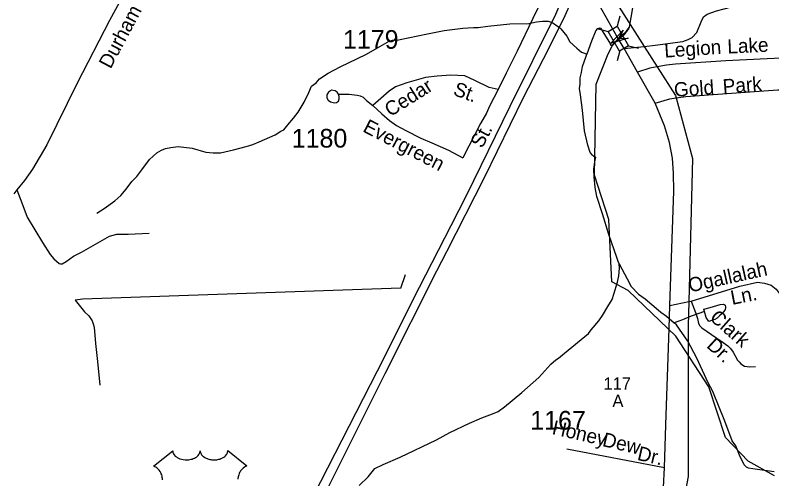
# Model space of a CAD drawing. Extents: x 2260773 to 2342389, y 552869 to 618546.
# Drawn here: x 2283170 to 2288230, y 568758 to 571861 of the extents above; entities that cross this region are included whole.
import ezdxf

# ---------------------------------------------------------------- set-up
doc = ezdxf.new("R2010")
doc.units = 0
for name, color, linetype in [('Exist Boundary Political Urban Extension UEB', 7, 'Continuous'), ('Exist Hydrographic Creek Single Shore', 7, 'Continuous'), ('Exist Hydrographic Misc Water Feature', 7, 'Continuous'), ('Exist Road Non-System Type 51', 7, 'Continuous'), ('Exist Road Non-System Type 51 Label', 7, 'Continuous'), ('Exist Road Primary US Attributed', 7, 'Continuous'), ('Exist Road Primary US Divided Attributed', 7, 'Continuous'), ('Exist Road Primary US Label', 7, 'Continuous'), ('Exist Road Primary US Shield CELL', 7, 'Continuous'), ('Exist Road Primary US Structure Standard Bridge CELL', 7, 'Continuous'), ('Exist Road Secondary Structure Standard Bridge Attributed CELL', 7, 'Continuous'), ('Exist Road Secondary Type 51 Attributed', 7, 'Continuous'), ('Exist Road Secondary Type 51 Label', 7, 'Continuous'), ('Exist Road Secondary Type 51 Number Label', 7, 'Continuous')]:
    doc.layers.add(name, color=color, linetype=linetype)

msp = doc.modelspace()

# ---------------------------------------------------------------- linework, layer by layer
at = {"layer": 'Exist Boundary Political Urban Extension UEB'}
msp.add_line((2287376.6, 571652.3), (2287464, 571515.1), dxfattribs=at)
for points in [[(2288406.6, 572860.4), (2287194.1, 571939.1), (2287376.6, 571652.3)], [(2287464, 571515.1), (2287586.5, 571322.6), (2287590.4, 571307.9)], [(2287590.4, 571307.9), (2287698.5, 570902.3), (2287674.6, 569943.9)], [(2287674.6, 569943.9), (2287670.5, 569781.5), (2287670.5, 568772.8), (2287558.4, 568184.4), (2287278.2, 567147.7), (2287255.6, 567057.4)]]:
    msp.add_lwpolyline(points, dxfattribs=at)
at = {"layer": 'Exist Hydrographic Creek Single Shore'}
for points in [[(2287160, 570075.5), (2287139.9, 570492.5), (2287044.9, 570789.5), (2287055.8, 571399.3), (2287135.6, 571602), (2287164.2, 571658.1), (2287204.2, 571703.8), (2287256.8, 571750.7), (2287278.5, 571781.6), (2287300.8, 571909.2)], [(2288246.9, 568777.9), (2288070.8, 568876.5), (2287919.9, 569033.7), (2287807.9, 569373.8), (2287587.9, 569712.7), (2287268.8, 570017.6), (2287160, 570075.5)]]:
    msp.add_lwpolyline(points, dxfattribs=at)
at = {"layer": 'Exist Hydrographic Misc Water Feature'}
for points in [[(2283715.5, 570536.2), (2283765.1, 570566.9), (2283836.3, 570619.4), (2283876.1, 570654), (2283911.5, 570696), (2283949.3, 570748.4), (2283983.1, 570781), (2284016.7, 570827), (2284067.6, 570895.6), (2284117.6, 570939.9), (2284149.4, 570958.2), (2284175, 570968.6), (2284210.9, 570975), (2284260.9, 570981.2), (2284353, 570970.2), (2284445.3, 570944.9), (2284494.9, 570939.5), (2284543.1, 570939.9), (2284630.6, 570958.8), (2284714.3, 570981.4), (2284758.4, 570995.9), (2284802.5, 571012.4), (2284908.1, 571059.3), (2284945.6, 571083.7), (2284967.7, 571093.7), (2284993, 571126), (2285031.1, 571170.6), (2285062.5, 571210.8), (2285103.5, 571278.8), (2285133, 571343.4), (2285152.7, 571385.4), (2285182.2, 571407.7), (2285205.8, 571433.8), (2285263.6, 571472.5), (2285343.4, 571515.2), (2285458.4, 571570.1), (2285520.6, 571600.9), (2285594, 571643.4), (2285671.5, 571688), (2285693.4, 571694.5), (2285733.2, 571696.6), (2285926.8, 571736.4), (2286038.3, 571757.7), (2286164.4, 571774.8), (2286234.6, 571779.2), (2286266.5, 571777.6), (2286330.1, 571786.4), (2286478, 571803.8), (2286605.9, 571804.8), (2286655.7, 571817.2), (2286695.5, 571819.7), (2286711.3, 571819.7), (2286733.5, 571820), (2286765.4, 571810.3), (2286773.8, 571802.2), (2286810.3, 571778.9), (2286820.2, 571768.9), (2286858.7, 571719.3), (2286878.6, 571681.4), (2286925.4, 571639.9), (2286957.2, 571614.4), (2286977.7, 571606.5), (2286993.7, 571600.8)], [(2287156.7, 571656.1), (2287146.8, 571677.9), (2287098, 571755.4), (2287096, 571761.4), (2287088, 571771.5), (2287078.1, 571773.4), (2287062.1, 571769.3), (2287053.9, 571759.2), (2287025, 571686.9), (2286993.7, 571600.8)], [(2287156.7, 571656.1), (2287196.9, 571690.6), (2287247.9, 571736.9), (2287260, 571750.9), (2287275.6, 571773.2)], [(2287054.2, 570909.6), (2287049.8, 570909.4), (2287038, 570917.3), (2287029.8, 570923.4), (2287015.6, 570941.4), (2286999.2, 570991.3), (2286978.3, 571086.9), (2286965, 571224.7), (2286950, 571328.4), (2286943.8, 571370.2), (2286949.2, 571400.3), (2286949, 571442.5), (2286956.8, 571476.2), (2286964.3, 571516.4), (2286987.5, 571586.7), (2286993.7, 571600.8)], [(2287204.7, 570205.2), (2287194.6, 570239.2), (2287141.1, 570392.9), (2287097.6, 570530.4), (2287060.7, 570647.8), (2287049.8, 570707.5), (2287043.1, 570779.5), (2287040.8, 570829.3), (2287046.2, 570879.6), (2287054.2, 570909.6)], [(2285471.4, 568714.1), (2285530.8, 568772.4), (2285576.3, 568826.8), (2285630.1, 568853.2), (2285743.7, 568902.2), (2285986.7, 569018.5), (2286075.8, 569067.5), (2286209.3, 569130.5), (2286290.9, 569167.3), (2286362.3, 569192.2), (2286400.2, 569208.4), (2286442.3, 569240.6), (2286559.2, 569335.7), (2286672.1, 569436.7), (2286753.1, 569525.5), (2286785.1, 569553.9), (2286802.8, 569565.8), (2286844.4, 569598.5), (2287005.1, 569731.7), (2287022.8, 569756.2), (2287072.4, 569814.4), (2287098, 569850.7), (2287133.1, 569911.1), (2287162.8, 569959.3), (2287174.5, 569993.3), (2287197.9, 570073.2), (2287207.5, 570117.6), (2287210.6, 570167.5), (2287209.2, 570196.8), (2287204.7, 570205.2)], [(2287204.7, 570205.2), (2287209.2, 570196.8), (2287263.3, 570095.8), (2287290.2, 570044.4), (2287338.4, 569994.9), (2287382.9, 569963.1), (2287471.6, 569886), (2287487.4, 569874.3), (2287525.8, 569846.7), (2287576.4, 569803)], [(2287779.4, 569879), (2287774.9, 569893.1), (2287817.4, 569905.4), (2287884.6, 569924), (2287904.9, 569926.2), (2287911.1, 569924.1), (2287918.9, 569920.5), (2287920.9, 569912.4), (2287920.9, 569902.3), (2287917.2, 569892.3), (2287909.2, 569878.1), (2287897.1, 569864.1), (2287879.7, 569848.1), (2287863.7, 569833.9), (2287847.9, 569823.7), (2287837.9, 569821.5), (2287808.1, 569811.4), (2287789.9, 569836.9), (2287779.4, 569879)], [(2287779.4, 569879), (2287689.8, 569846.3), (2287633.8, 569821.5), (2287608.2, 569813.5), (2287576.4, 569803)], [(2288245.3, 568804), (2288103.2, 568824.5), (2288074.9, 568830.4), (2288061, 568836.2), (2288045, 568852), (2288014.4, 568915.8), (2287989.6, 568979.5), (2287965.6, 569013.2), (2287916, 569144.7), (2287834.6, 569341.9), (2287803.6, 569401.3), (2287728.4, 569564.7), (2287667.3, 569679.8), (2287592.4, 569789.2), (2287576.4, 569803)]]:
    msp.add_lwpolyline(points, dxfattribs=at)
at = {"layer": 'Exist Road Non-System Type 51'}
for p, q in [((2287242, 571636.8), (2287376.6, 571652.3)), ((2285749, 570033.8), (2285780.3, 570126.1)), ((2287547.7, 569918.3), (2287674.6, 569943.9)), ((2287674.6, 569943.9), (2287691.1, 569947.2))]:
    msp.add_line(p, q, dxfattribs=at)
for points in [[(2287376.6, 571652.3), (2287450.9, 571660.9), (2287634.5, 571684.6), (2287670.3, 571697.1), (2287698.2, 571711.3), (2287727.9, 571745.5), (2287757.3, 571815.7), (2287773, 571849.9), (2287796.7, 571868), (2287860.5, 571890.7), (2287962.2, 571917.7), (2288029.8, 571964.3), (2288091.2, 572016.8), (2288114.9, 572040.9), (2288142.7, 572053.2), (2288164.7, 572053.3), (2288206.9, 572041.9), (2288259.1, 572016.2), (2288317.2, 571990.9), (2288381.4, 571981.6), (2288443.1, 571990.1), (2288479.2, 572002.4), (2288508.8, 572026.6), (2288511, 572030.6)], [(2288471.9, 571580.3), (2288337.2, 571575.2), (2287921.5, 571555.4), (2287586, 571532.2), (2287526.1, 571525.7), (2287464, 571515.1)], [(2287464, 571515.1), (2287414.4, 571506.7), (2287331.1, 571479.2)], [(2285333, 571331.3), (2285322.9, 571345.1), (2285308.9, 571355), (2285284.8, 571358.7), (2285265.1, 571344.7), (2285253.2, 571328.5), (2285253.4, 571308.5), (2285263.5, 571292.5), (2285279.6, 571280.8), (2285295.8, 571276.9), (2285307.7, 571275), (2285319.6, 571277.2), (2285331.5, 571285.1), (2285337.4, 571301.2), (2285337.4, 571317.2), (2285333, 571331.3)], [(2287590.4, 571307.9), (2287656, 571317.1), (2287961.5, 571337.9), (2288269.3, 571360.9), (2288399, 571362.1), (2288453.7, 571370.3)], [(2285333, 571331.3), (2285403.2, 571332.5), (2285456.8, 571326.7), (2285478, 571321.7), (2285498, 571311.9), (2285520, 571290.3), (2285562.1, 571255.9)], [(2287449.6, 571271.5), (2287548.2, 571302.1), (2287590.4, 571307.9)], [(2283182.2, 570691), (2283215.4, 570604.2), (2283249.2, 570510.3), (2283352.6, 570340.5), (2283404.9, 570260.1), (2283427.8, 570230.7), (2283463.6, 570200.1), (2283472.5, 570196.3), (2283485.3, 570197.5), (2283512.1, 570212.9), (2283560.5, 570247.3), (2283614, 570275.7), (2283800.4, 570381.4), (2283850.2, 570395.4), (2283925.5, 570395.4), (2284067.1, 570403.1)], [(2287691.1, 569947.2), (2288015.9, 570047.3), (2288134.3, 570074.9), (2288181.5, 570066.8), (2288225.4, 570053.1), (2288259.7, 570027.4), (2288298.7, 569973.6)], [(2285749, 570033.8), (2283621, 569959.9), (2283571.1, 569953.5), (2283633.7, 569876), (2283661.9, 569848.3), (2283684.2, 569814.6), (2283692.4, 569794.7), (2283698.8, 569772.7), (2283707.8, 569664.8), (2283720.9, 569543), (2283736.3, 569385.3)], [(2287691.1, 569947.2), (2287718.7, 569872.2), (2287733.1, 569831.4), (2287739.7, 569798.5), (2287747.6, 569782.7), (2287762.1, 569769.6), (2287862, 569699.8), (2287905.5, 569669.5), (2287937, 569648.5), (2287954.1, 569631.4), (2287971.2, 569606.4), (2288001.5, 569552.4), (2288012, 569540.6), (2288022.5, 569528.7), (2288047.5, 569512.9), (2288083, 569507.7), (2288119.9, 569510.3)]]:
    msp.add_lwpolyline(points, dxfattribs=at)
at = {"layer": 'Exist Road Primary US Attributed'}
for points in [[(2287196.9, 571715.9), (2287076.2, 571930.2), (2287035.8, 572001.3)], [(2287512.2, 568832.5), (2287521.5, 569120.3), (2287542.6, 569763.6), (2287547.7, 569918.3), (2287574.9, 570683.2), (2287572.2, 570804.5), (2287565.2, 570903.5), (2287545.7, 571009.4), (2287512.3, 571121), (2287449.6, 571271.5), (2287331.1, 571479.2), (2287242, 571636.8), (2287196.9, 571715.9)], [(2287018.9, 566693.9), (2287122, 567057.4), (2287159.7, 567190.1), (2287281, 567619.5), (2287342.7, 567854), (2287396.4, 568031.7), (2287443.8, 568215.9), (2287480.6, 568403.5), (2287496.4, 568528.5), (2287500.3, 568606.2), (2287505.6, 568701.6), (2287512.2, 568832.5)]]:
    msp.add_lwpolyline(points, dxfattribs=at)
at = {"layer": 'Exist Road Primary US Divided Attributed'}
for points in [[(2286878.6, 572105.8), (2286833, 571982.2), (2286782.4, 571865.7), (2286477.4, 571248.9), (2286185.2, 570652), (2286082.6, 570450.1), (2285871.7, 570038.9), (2285590.6, 569478.9), (2285164.4, 568647.3), (2284873.8, 568065.7), (2284671.9, 567618.8), (2284548.2, 567284.9), (2284478.2, 567045.3), (2284416.3, 566789.5), (2284365.2, 566533.7), (2284322.1, 566259.1), (2284289.8, 565936), (2284268.3, 565564.5), (2284273.7, 565214.4)], [(2284365.2, 565206.4), (2284354.4, 565561.8), (2284370.6, 565952.2), (2284397.5, 566242.9), (2284443.2, 566531), (2284491.7, 566784.1), (2284556.2, 567048), (2284618.1, 567263.4), (2284736.5, 567594.5), (2284938.3, 568065.7), (2285215.5, 568606.9), (2285643.3, 569463.1), (2285990.5, 570149.7), (2286057.7, 570278.9), (2286308, 570774.3), (2286569, 571310.1), (2286703.5, 571568.6), (2286838.1, 571837.8), (2286893.8, 571965.3), (2286930.4, 572091.7)]]:
    msp.add_lwpolyline(points, dxfattribs=at)
at = {"layer": 'Exist Road Primary US Shield CELL'}
msp.add_lwpolyline([(2284155, 568751.7), (2284154.7, 568759.3), (2284153.7, 568768.2), (2284152.1, 568776.7), (2284150.1, 568784.2), (2284146.9, 568792.7), (2284143.9, 568798.9), (2284139, 568807.4), (2284133.5, 568815.2), (2284127.9, 568821.6), (2284122.2, 568827.3), (2284116.7, 568831.5), (2284111.5, 568835.3), (2284105, 568839.2), (2284098.7, 568842.3), (2284094.7, 568843.9), (2284223.3, 568946.4), (2284223.6, 568941), (2284224.9, 568934.7), (2284225.9, 568931.5), (2284228.9, 568925.2), (2284233.7, 568917.9), (2284240.5, 568910.6), (2284248.2, 568904.3), (2284253.4, 568901), (2284262.1, 568896.3), (2284272.1, 568892.1), (2284283.2, 568888.9), (2284294.5, 568886.6), (2284306.9, 568885.3), (2284319.1, 568885), (2284332.3, 568886), (2284346.9, 568888.8), (2284353.7, 568890.6), (2284361.2, 568893.2), (2284368.2, 568896), (2284375.8, 568900.1), (2284382, 568904.1), (2284386.8, 568907.6), (2284393.7, 568914.1), (2284399.1, 568920.9), (2284401.4, 568924.7), (2284403.3, 568928.3), (2284406, 568936.1), (2284406.8, 568939.5), (2284407.3, 568946.6), (2284407.8, 568940.6), (2284408.4, 568936.9), (2284409.4, 568933.3), (2284410.9, 568929.4), (2284413.6, 568923.9), (2284416.7, 568919.4), (2284422.4, 568912.6), (2284426, 568909.3), (2284429.2, 568906.6), (2284438, 568900.6), (2284448.2, 568895.4), (2284453.2, 568893.2), (2284458.4, 568891.4), (2284464.9, 568889.4), (2284471.6, 568887.8), (2284478.3, 568886.7), (2284485.2, 568885.7), (2284492.2, 568885.2), (2284497.9, 568885), (2284504.8, 568885.1), (2284511.3, 568885.5), (2284517.9, 568886.2), (2284525.2, 568887.5), (2284531, 568888.7), (2284538.8, 568890.8), (2284545.8, 568893.3), (2284551.9, 568896), (2284559.9, 568900.1), (2284566.4, 568904.2), (2284571.1, 568908), (2284576.7, 568913.1), (2284582, 568919.3), (2284585.1, 568923.8), (2284587.3, 568928.4), (2284589.4, 568933.3), (2284590.6, 568938.4), (2284591.2, 568942.9), (2284591.4, 568946.8), (2284720, 568844.3), (2284716.9, 568843.2), (2284709.9, 568839.7), (2284704.4, 568836.5), (2284695.5, 568830.2), (2284691.7, 568826.8), (2284688, 568823.2), (2284684.5, 568819.4), (2284681.4, 568815.9), (2284677.7, 568810.7), (2284674.3, 568805.5), (2284671.1, 568799.8), (2284668.7, 568794.9), (2284664.7, 568784.6), (2284662.8, 568778), (2284661.6, 568772.5), (2284660.1, 568761), (2284659.7, 568755.5)], dxfattribs=at)
at = {"layer": 'Exist Road Primary US Structure Standard Bridge CELL'}
for p, q in [((2287213.3, 571854), (2287195.9, 571787.2)), ((2287068.3, 571768.9), (2287135, 571751.5)), ((2287272.1, 571656.7), (2287338.8, 571639.3)), ((2287212.6, 571621.8), (2287195.1, 571555))]:
    msp.add_line(p, q, dxfattribs=at)
msp.add_lwpolyline([(2287195.9, 571787.2), (2287272.4, 571656.8), (2287211.5, 571621.1), (2287135, 571751.5)], close=True, dxfattribs=at)
at = {"layer": 'Exist Road Secondary Structure Standard Bridge Attributed CELL'}
msp.add_lwpolyline([(2287269.2, 571706.2), (2287152.1, 571672.3), (2287236.5, 571760.2), (2287204.2, 571703.8)], close=True, dxfattribs=at)
at = {"layer": 'Exist Road Secondary Type 51 Attributed'}
msp.add_line((2287512.2, 568832.5), (2286859.8, 568956.2), dxfattribs=at)
for points in [[(2284020.5, 572221.7), (2283936.9, 572076.8), (2283799.8, 571825.9), (2283585.4, 571405.9), (2283381.3, 570992.3), (2283285.6, 570830.1), (2283232, 570754.8), (2283182.2, 570691), (2283160.6, 570665.1)], [(2286878.6, 572105.8), (2286842.1, 572112.9), (2286808.7, 572112.9), (2286779.4, 572101.7), (2286752.5, 572075.5), (2286729.6, 572042.9), (2286722.8, 572028.8), (2286631.9, 571838), (2286527.6, 571620.7), (2286453, 571473.2), (2286399.4, 571364)], [(2286399.4, 571364), (2286340.1, 571377.5), (2286244.4, 571423.4), (2286177.4, 571454.1), (2286083.6, 571459.8), (2285991.6, 571453.3), (2285913.9, 571442.7), (2285788.2, 571407.5), (2285714.5, 571380.8), (2285670.7, 571352.5), (2285615.2, 571303.8), (2285562.1, 571255.9)], [(2286399.4, 571364), (2286342, 571253), (2286320.9, 571205.1), (2286282.7, 571136.2), (2286163.5, 570906.5)], [(2285562.1, 571255.9), (2285622.4, 571201.7), (2285674.2, 571156.8), (2285719.9, 571123.7), (2285783.5, 571088.9), (2285883.6, 571038.9), (2285955.6, 571005.8), (2286068.4, 570956.6), (2286163.5, 570906.5)]]:
    msp.add_lwpolyline(points, dxfattribs=at)

# ---------------------------------------------------------------- texts
at = {"layer": 'Exist Road Non-System Type 51 Label'}
for s, rotation, p in [('Legion', 3.9556, (2287514, 571576.5)), ('Lake', 2.7269, (2287934.7, 571603.6)), ('Park', 4.2738, (2287905, 571336.7)), ('Gold', 3.8951, (2287579.1, 571314.7)), ('Ogallalah', 12.4976, (2287683, 570005)), ('Ln.', 11.2056, (2287964.5, 569922)), ('Clark', 318.5653, (2287807.9, 569827.6)), ('Dr.', 317.4378, (2287788.2, 569642.8))]:
    msp.add_text(s, height=95, rotation=rotation, dxfattribs=at).set_placement(p)
at = {"layer": 'Exist Road Primary US Label'}
for s, height, p in [('117', 82.02, (2287104.7, 569354.7)), ('A', 82, (2287164.4, 569239.9))]:
    msp.add_text(s, height=height, dxfattribs=at).set_placement(p)
at = {"layer": 'Exist Road Secondary Type 51 Label'}
for s, rotation, p in [('Durham', 62.0521, (2283808.1, 571496.7)), ('Cedar', 32.2086, (2285678.6, 571178)), ('St.', 339.9288, (2286093, 571328.9)), ('Evergreen', 332.5647, (2285488.7, 571084.9)), ('St.', 62.0771, (2286292.6, 570964.7)), ('Honey', 347.0621, (2286755.5, 569058.6)), ('Dew', 347.0621, (2287091.8, 568977.9)), ('Dr.', 347.0621, (2287325.2, 568885.7))]:
    msp.add_text(s, height=95, rotation=rotation, dxfattribs=at).set_placement(p)
at = {"layer": 'Exist Road Secondary Type 51 Number Label'}
for s, p in [('1179', (2285362, 571636.1)), ('1180', (2285019.3, 570974.8)), ('1167', (2286614.4, 569087.7))]:
    msp.add_text(s, height=125, dxfattribs=at).set_placement(p)

doc.saveas('drawing.dxf')
